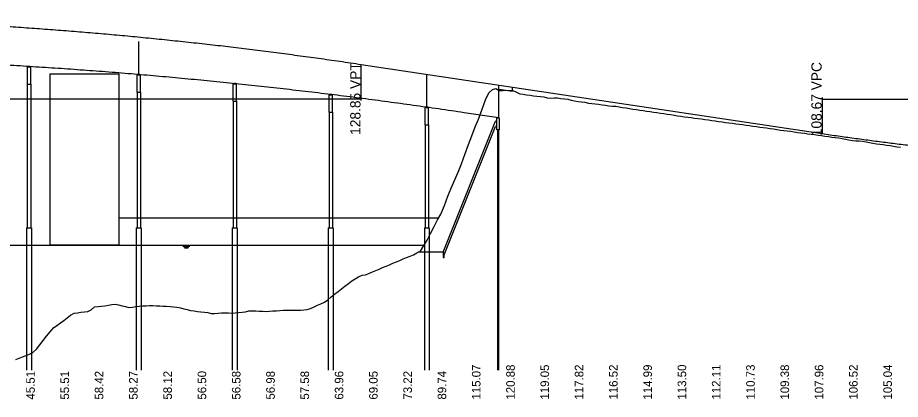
# Model space of a CAD drawing. Extents: x 2121671 to 2169879, y 557274 to 599957.
# Drawn here: x 2155742 to 2157029, y 595763 to 596320 of the extents above; entities that cross this region are included whole.
import ezdxf

# ---------------------------------------------------------------- set-up
doc = ezdxf.new("R2010")
doc.units = 0
for name, color, linetype in [('BR_CONCRETE', 7, 'Continuous'), ('BR_DETAILS', 7, 'Continuous'), ('BR_PRESTRESSED BEAM', 7, 'Continuous'), ('BR_STRUCTURAL STEEL', 7, 'Continuous'), ('RD_DDB_Profile_Elev', 7, 'Continuous'), ('RD_DDB_Profile_EX', 7, 'Continuous'), ('RD_DDB_Profile_PR', 7, 'Continuous'), ('RD_DDB_StripGrade', 7, 'Continuous'), ('RD_DDB_VCLbl', 7, 'Continuous')]:
    doc.layers.add(name, color=color, linetype=linetype)

msp = doc.modelspace()

# ---------------------------------------------------------------- linework, layer by layer
at = {"layer": 'BR_CONCRETE'}
for p, q in [((2155756.3, 596222.8), (2155756.3, 596013.1)), ((2155756.3, 596222.8), (2155756.3, 596013.1)), ((2155761.3, 596222.8), (2155761.3, 596013.1)), ((2155761.3, 596222.8), (2155761.3, 596013.1)), ((2156443.8, 596215.8), (2156463.8, 596212.8)), ((2156443.8, 596215.8), (2156463.8, 596212.8)), ((2156463.8, 596212.8), (2156463.8, 596218.6)), ((2156463.8, 596212.8), (2156463.8, 596218.6)), ((2155916.3, 596211.1), (2155916.3, 596013.1)), ((2155916.3, 596211.1), (2155916.3, 596013.1)), ((2155921.3, 596211.1), (2155921.3, 596013.1)), ((2155921.3, 596211.1), (2155921.3, 596013.1)), ((2156056.3, 596197.9), (2156056.3, 596013.1)), ((2156056.3, 596197.9), (2156056.3, 596013.1)), ((2156061.3, 596197.9), (2156061.3, 596013.1)), ((2156061.3, 596197.9), (2156061.3, 596013.1)), ((2156196.3, 596182), (2156196.3, 596013.1)), ((2156196.3, 596182), (2156196.3, 596013.1)), ((2156201.3, 596182), (2156201.3, 596013.1)), ((2156201.3, 596182), (2156201.3, 596013.1)), ((2156336.3, 596163.4), (2156336.3, 596013.1)), ((2156336.3, 596163.4), (2156336.3, 596013.1)), ((2156341.3, 596163.4), (2156341.3, 596013.1)), ((2156341.3, 596163.4), (2156341.3, 596013.1)), ((2155755.3, 596013.1), (2155755.3, 595805.8)), ((2155755.3, 596013.1), (2155755.3, 595805.8)), ((2155762.3, 596013.1), (2155762.3, 595805.8)), ((2155762.3, 596013.1), (2155762.3, 595805.8)), ((2155915.3, 596013.1), (2155915.3, 595805.8)), ((2155915.3, 596013.1), (2155915.3, 595805.8)), ((2155922.3, 596013.1), (2155922.3, 595805.8)), ((2155922.3, 596013.1), (2155922.3, 595805.8)), ((2156055.3, 596013.1), (2156055.3, 595805.8)), ((2156055.3, 596013.1), (2156055.3, 595805.8)), ((2156062.3, 596013.1), (2156062.3, 595805.8)), ((2156062.3, 596013.1), (2156062.3, 595805.8)), ((2156195.3, 596013.1), (2156195.3, 595805.8)), ((2156195.3, 596013.1), (2156195.3, 595805.8)), ((2156202.3, 596013.1), (2156202.3, 595805.8)), ((2156202.3, 596013.1), (2156202.3, 595805.8)), ((2156335.3, 596013.1), (2156335.3, 595805.8)), ((2156335.3, 596013.1), (2156335.3, 595805.8)), ((2156342.3, 596013.1), (2156342.3, 595805.8)), ((2156342.3, 596013.1), (2156342.3, 595805.8))]:
    msp.add_line(p, q, dxfattribs=at)
for points in [[(2155756.1, 596222.8), (2155761.6, 596222.8), (2155761.6, 596247.8), (2155756.1, 596247.8)], [(2155756.1, 596222.8), (2155761.6, 596222.8), (2155761.6, 596247.8), (2155756.1, 596247.8)], [(2155916.1, 596211.1), (2155921.6, 596211.1), (2155921.6, 596236.1), (2155916.1, 596236.1)], [(2155916.1, 596211.1), (2155921.6, 596211.1), (2155921.6, 596236.1), (2155916.1, 596236.1)], [(2156056.1, 596197.9), (2156061.6, 596197.9), (2156061.6, 596222.9), (2156056.1, 596222.9)], [(2156056.1, 596197.9), (2156061.6, 596197.9), (2156061.6, 596222.9), (2156056.1, 596222.9)], [(2156196.1, 596182), (2156201.6, 596182), (2156201.6, 596207), (2156196.1, 596207)], [(2156196.1, 596182), (2156201.6, 596182), (2156201.6, 596207), (2156196.1, 596207)], [(2156336.1, 596163.4), (2156341.6, 596163.4), (2156341.6, 596188.4), (2156336.1, 596188.4)], [(2156336.1, 596163.4), (2156341.6, 596163.4), (2156341.6, 596188.4), (2156336.1, 596188.4)], [(2156444.5, 596156.3), (2156441, 596156.3), (2156441, 596173.8), (2156444.5, 596173.8)], [(2156444.5, 596156.3), (2156441, 596156.3), (2156441, 596173.8), (2156444.5, 596173.8)]]:
    msp.add_lwpolyline(points, close=True, dxfattribs=at)
at = {"layer": 'BR_DETAILS'}
for p, q in [((2156362.6, 595977.7), (2156439, 596168.8)), ((2156362.6, 595977.7), (2156439, 596168.8)), ((2156441, 596168.8), (2156439, 596168.8)), ((2156441, 596168.8), (2156439, 596168.8)), ((2156364.1, 595974), (2156439, 596161.3)), ((2156364.1, 595974), (2156439, 596161.3)), ((2156441, 596161.3), (2156439, 596161.3)), ((2156441, 596161.3), (2156439, 596161.3)), ((2156362.6, 595977.7), (2156326.5, 595977.7)), ((2156362.6, 595977.7), (2156326.5, 595977.7)), ((2156362.6, 595977.7), (2156362.6, 595970.2)), ((2156362.6, 595977.7), (2156362.6, 595970.2)), ((2156364.1, 595970.2), (2156364.1, 595974)), ((2156364.1, 595970.2), (2156364.1, 595974)), ((2156362.6, 595970.2), (2156364.1, 595970.2)), ((2156362.6, 595970.2), (2156364.1, 595970.2))]:
    msp.add_line(p, q, dxfattribs=at)
for points in [[(2155757.3, 596249.1), (2155758.3, 596249.1), (2155758.3, 596247.8), (2155757.3, 596247.8)], [(2155757.3, 596249.1), (2155758.3, 596249.1), (2155758.3, 596247.8), (2155757.3, 596247.8)], [(2155759.3, 596249.1), (2155760.3, 596249.1), (2155760.3, 596247.8), (2155759.3, 596247.8)], [(2155759.3, 596249.1), (2155760.3, 596249.1), (2155760.3, 596247.8), (2155759.3, 596247.8)], [(2155917.3, 596237.3), (2155918.3, 596237.3), (2155918.3, 596236.1), (2155917.3, 596236.1)], [(2155917.3, 596237.3), (2155918.3, 596237.3), (2155918.3, 596236.1), (2155917.3, 596236.1)], [(2155919.3, 596237.3), (2155920.3, 596237.3), (2155920.3, 596236.1), (2155919.3, 596236.1)], [(2155919.3, 596237.3), (2155920.3, 596237.3), (2155920.3, 596236.1), (2155919.3, 596236.1)], [(2156057.3, 596224.2), (2156058.3, 596224.2), (2156058.3, 596222.9), (2156057.3, 596222.9)], [(2156057.3, 596224.2), (2156058.3, 596224.2), (2156058.3, 596222.9), (2156057.3, 596222.9)], [(2156059.3, 596224.2), (2156060.3, 596224.2), (2156060.3, 596222.9), (2156059.3, 596222.9)], [(2156059.3, 596224.2), (2156060.3, 596224.2), (2156060.3, 596222.9), (2156059.3, 596222.9)], [(2156197.3, 596208.3), (2156198.3, 596208.3), (2156198.3, 596207), (2156197.3, 596207)], [(2156197.3, 596208.3), (2156198.3, 596208.3), (2156198.3, 596207), (2156197.3, 596207)], [(2156199.3, 596208.3), (2156200.3, 596208.3), (2156200.3, 596207), (2156199.3, 596207)], [(2156199.3, 596208.3), (2156200.3, 596208.3), (2156200.3, 596207), (2156199.3, 596207)], [(2156337.3, 596189.7), (2156338.3, 596189.7), (2156338.3, 596188.4), (2156337.3, 596188.4)], [(2156337.3, 596189.7), (2156338.3, 596189.7), (2156338.3, 596188.4), (2156337.3, 596188.4)], [(2156339.3, 596189.7), (2156340.3, 596189.7), (2156340.3, 596188.4), (2156339.3, 596188.4)], [(2156339.3, 596189.7), (2156340.3, 596189.7), (2156340.3, 596188.4), (2156339.3, 596188.4)], [(2156442.2, 596174.2), (2156443.2, 596174.2), (2156443.2, 596173.8), (2156442.2, 596173.8)], [(2156442.2, 596174.2), (2156443.2, 596174.2), (2156443.2, 596173.8), (2156442.2, 596173.8)]]:
    msp.add_lwpolyline(points, close=True, dxfattribs=at)
at = {"layer": 'BR_PRESTRESSED BEAM'}
for p, q in [((2155918.8, 596237.5), (2155918.8, 596285)), ((2155918.8, 596237.5), (2155918.8, 596285)), ((2156338.8, 596189.9), (2156338.8, 596237.4)), ((2156338.8, 596189.9), (2156338.8, 596237.4)), ((2156443.8, 596174.1), (2156443.8, 596221.6)), ((2156443.8, 596174.1), (2156443.8, 596221.6)), ((2156393.2, 596181.7), (2156443.8, 596174.1)), ((2156393.2, 596181.7), (2156443.8, 596174.1)), ((2155755.3, 596013.1), (2155762.3, 596013.1)), ((2155755.3, 596013.1), (2155762.3, 596013.1)), ((2155915.3, 596013.1), (2155922.3, 596013.1)), ((2155915.3, 596013.1), (2155922.3, 596013.1)), ((2156055.3, 596013.1), (2156062.3, 596013.1)), ((2156055.3, 596013.1), (2156062.3, 596013.1)), ((2156195.3, 596013.1), (2156202.3, 596013.1)), ((2156195.3, 596013.1), (2156202.3, 596013.1)), ((2156335.3, 596013.1), (2156342.3, 596013.1)), ((2156335.3, 596013.1), (2156342.3, 596013.1))]:
    msp.add_line(p, q, dxfattribs=at)
msp.add_spline([(2154543.2, 596222.7), (2154580.2, 596226.6), (2154617.2, 596230.2), (2154654.2, 596233.6), (2154691.2, 596236.9), (2154728.2, 596239.9), (2154765.2, 596242.8), (2154802.2, 596245.5), (2154839.2, 596248), (2154876.2, 596250.3), (2154913.2, 596252.4), (2154950.2, 596254.3), (2154987.2, 596256), (2155024.2, 596257.6), (2155061.2, 596258.9), (2155098.2, 596260.1), (2155135.2, 596261.1), (2155172.2, 596261.9), (2155209.2, 596262.5), (2155246.2, 596262.9), (2155283.2, 596263.1), (2155320.2, 596263.1), (2155357.2, 596263), (2155394.2, 596262.6), (2155431.2, 596262.1), (2155468.2, 596261.3), (2155505.2, 596260.4), (2155542.2, 596259.3), (2155579.2, 596258), (2155616.2, 596256.5), (2155653.2, 596254.9), (2155690.2, 596253), (2155727.2, 596251), (2155764.2, 596248.7), (2155801.2, 596246.3), (2155838.2, 596243.7), (2155875.2, 596240.9), (2155912.2, 596237.9), (2155949.2, 596234.7), (2155986.2, 596231.3), (2156023.2, 596227.7), (2156060.2, 596224), (2156097.2, 596220.1), (2156134.2, 596215.9), (2156171.2, 596211.6), (2156208.2, 596207.1), (2156245.2, 596202.4), (2156282.2, 596197.5), (2156319.2, 596192.4), (2156356.2, 596187.2), (2156393.2, 596181.7)], degree=3, dxfattribs=at)
msp.add_spline([(2154543.2, 596222.7), (2154580.2, 596226.6), (2154617.2, 596230.2), (2154654.2, 596233.6), (2154691.2, 596236.9), (2154728.2, 596239.9), (2154765.2, 596242.8), (2154802.2, 596245.5), (2154839.2, 596248), (2154876.2, 596250.3), (2154913.2, 596252.4), (2154950.2, 596254.3), (2154987.2, 596256), (2155024.2, 596257.6), (2155061.2, 596258.9), (2155098.2, 596260.1), (2155135.2, 596261.1), (2155172.2, 596261.9), (2155209.2, 596262.5), (2155246.2, 596262.9), (2155283.2, 596263.1), (2155320.2, 596263.1), (2155357.2, 596263), (2155394.2, 596262.6), (2155431.2, 596262.1), (2155468.2, 596261.3), (2155505.2, 596260.4), (2155542.2, 596259.3), (2155579.2, 596258), (2155616.2, 596256.5), (2155653.2, 596254.9), (2155690.2, 596253), (2155727.2, 596251), (2155764.2, 596248.7), (2155801.2, 596246.3), (2155838.2, 596243.7), (2155875.2, 596240.9), (2155912.2, 596237.9), (2155949.2, 596234.7), (2155986.2, 596231.3), (2156023.2, 596227.7), (2156060.2, 596224), (2156097.2, 596220.1), (2156134.2, 596215.9), (2156171.2, 596211.6), (2156208.2, 596207.1), (2156245.2, 596202.4), (2156282.2, 596197.5), (2156319.2, 596192.4), (2156356.2, 596187.2), (2156393.2, 596181.7)], degree=3, dxfattribs=at)
at = {"layer": 'BR_STRUCTURAL STEEL'}
for p, q in [((2156442.2, 596156.3), (2156442.2, 595805.5)), ((2156442.2, 596156.3), (2156442.2, 595805.5)), ((2156443.3, 596156.3), (2156443.3, 595805.5)), ((2156443.3, 596156.3), (2156443.3, 595805.5))]:
    msp.add_line(p, q, dxfattribs=at)
at = {"layer": 'RD_DDB_Profile_Elev'}
for p, q in [((2155889.7, 596028.1), (2156356.4, 596028.1)), ((2151972, 595988.1), (2156334.9, 595988.1)), ((2155983.2, 595986.8), (2155993.2, 595986.8)), ((2155984.4, 595985.6), (2155991.9, 595985.6)), ((2155985.7, 595984.3), (2155990.7, 595984.3))]:
    msp.add_line(p, q, dxfattribs=at)
msp.add_lwpolyline([(2155789.7, 596238.1), (2155889.7, 596238.1), (2155889.7, 595988.1), (2155789.7, 595988.1)], close=True, dxfattribs=at)
at = {"layer": 'RD_DDB_Profile_EX'}
for points in [[(2156194.5, 595908.4), (2156199.5, 595912.4), (2156204.5, 595916.4), (2156209.5, 595920.4), (2156214.5, 595924.3), (2156219.5, 595928.2), (2156224.5, 595932.1), (2156229.5, 595935.9), (2156234.5, 595939.1), (2156239.5, 595941.9), (2156244.5, 595944.4), (2156249.5, 595944.9), (2156254.5, 595946.9), (2156259.5, 595949), (2156264.5, 595951.1), (2156269.5, 595953.2), (2156274.5, 595955.3), (2156279.5, 595957.4), (2156284.5, 595959.5), (2156289.5, 595961.6), (2156294.5, 595963.7), (2156299.5, 595965.8), (2156304.5, 595967.9), (2156309.5, 595969.9), (2156314.5, 595972), (2156319.5, 595974.1), (2156324.5, 595976.7), (2156329.5, 595979.2), (2156334.5, 595987.3), (2156339.5, 595995.5), (2156344.5, 596005.2), (2156349.5, 596015.4), (2156354.5, 596024.8), (2156359.5, 596033.2), (2156364.5, 596046.1), (2156369.5, 596059.5), (2156374.5, 596071.4), (2156379.5, 596082.4), (2156384.5, 596094.5), (2156389.5, 596106.8), (2156394.5, 596120.1), (2156399.5, 596134.9), (2156404.5, 596147.6), (2156409.5, 596160.6), (2156414.5, 596172), (2156419.5, 596186.4), (2156424.5, 596200.1), (2156429.5, 596210.1), (2156434.5, 596214.9), (2156439.5, 596216.5), (2156444.5, 596213.5), (2156449.5, 596213.7), (2156454.5, 596214.2), (2156459.5, 596213.7), (2156464.5, 596213.7), (2156469.5, 596211.3), (2156474.5, 596209), (2156479.5, 596208.1), (2156484.5, 596207.4), (2156489.5, 596206.6), (2156494.5, 596205.7), (2156499.5, 596205.4), (2156504.5, 596205), (2156509.5, 596204.2), (2156514.5, 596202.8), (2156519.5, 596202.7), (2156524.5, 596202.9), (2156529.5, 596202.8), (2156534.5, 596202.1), (2156539.5, 596201.7), (2156544.5, 596201.2), (2156549.5, 596199.6), (2156554.5, 596198.5), (2156559.5, 596197.8), (2156564.5, 596197.1), (2156569.5, 596196.4), (2156574.5, 596195.4), (2156579.5, 596194.9), (2156584.5, 596194.2), (2156589.5, 596193.5), (2156594.5, 596192.9), (2156599.5, 596192.2), (2156604.5, 596191.3), (2156609.5, 596190.7), (2156614.5, 596190.7), (2156619.5, 596189.9), (2156624.5, 596189), (2156629.5, 596188.2), (2156634.5, 596187.4), (2156639.5, 596186.6), (2156644.5, 596185.8), (2156649.5, 596185.1), (2156654.5, 596184.4), (2156659.5, 596183.7), (2156664.5, 596183), (2156669.5, 596182.2), (2156674.5, 596181.5), (2156679.5, 596180.7), (2156684.5, 596180), (2156689.5, 596179.2), (2156694.5, 596178.5)], [(2156694.5, 596178.5), (2156699.5, 596177.7), (2156704.5, 596176.9), (2156709.5, 596176.2), (2156714.5, 596175.4), (2156719.5, 596174.8), (2156724.5, 596174.1), (2156729.5, 596173.5), (2156734.5, 596172.8), (2156739.5, 596172.1), (2156744.5, 596171.5), (2156749.5, 596170.7), (2156754.5, 596170), (2156759.5, 596169.4), (2156764.5, 596168.6), (2156769.5, 596167.9), (2156774.5, 596167.1), (2156779.5, 596166.4), (2156784.5, 596165.9), (2156789.5, 596165), (2156794.5, 596164.6), (2156799.5, 596163.9), (2156804.5, 596163.2), (2156809.5, 596162.5), (2156814.5, 596161.7), (2156819.5, 596160.9), (2156824.5, 596160.2), (2156829.5, 596159.6), (2156834.5, 596159), (2156839.5, 596158.4), (2156844.5, 596157.6), (2156849.5, 596156.8), (2156854.5, 596155.9), (2156859.5, 596155.3), (2156864.5, 596154.9), (2156869.5, 596154.2), (2156874.5, 596153.4), (2156879.5, 596152.5), (2156884.5, 596151.9), (2156889.5, 596151.2), (2156894.5, 596150.6), (2156899.5, 596150.1), (2156904.5, 596149.4), (2156909.5, 596148.7), (2156914.5, 596147.9), (2156919.5, 596147.1), (2156924.5, 596146.3), (2156929.5, 596145.4), (2156934.5, 596145.3), (2156939.5, 596144.5), (2156944.5, 596143.7), (2156949.5, 596142.7), (2156954.5, 596141.7), (2156959.5, 596140.9), (2156964.5, 596140.4), (2156969.5, 596140), (2156974.5, 596139.5), (2156979.5, 596138.7), (2156984.5, 596137.7), (2156989.5, 596136.6), (2156994.5, 596135.8), (2156999.5, 596135.6), (2157004.5, 596134.8), (2157009.5, 596134.1), (2157014.5, 596133.3), (2157019.5, 596132.4), (2157024.5, 596131.6), (2157029.5, 596131)], [(2155739.5, 595821.3), (2155744.5, 595823.3), (2155749.5, 595825.3), (2155754.5, 595827.2), (2155759.5, 595829.2), (2155764.5, 595831.4), (2155769.5, 595836.2), (2155774.5, 595842.6), (2155779.5, 595849), (2155784.5, 595855.3), (2155789.5, 595861.7), (2155794.5, 595867.2), (2155799.5, 595870.7), (2155804.5, 595874.5), (2155809.5, 595878.3), (2155814.5, 595882.1), (2155819.5, 595886), (2155824.5, 595888.9), (2155829.5, 595889.5), (2155834.5, 595890.1), (2155839.5, 595890.7), (2155844.5, 595891.3), (2155849.5, 595893.7), (2155854.5, 595897.9), (2155859.5, 595898.5), (2155864.5, 595899.1), (2155869.5, 595899.7), (2155874.5, 595900.3), (2155879.5, 595901.4), (2155884.5, 595902), (2155889.5, 595900.8), (2155894.5, 595899.5), (2155899.5, 595898.3), (2155904.5, 595897), (2155909.5, 595897.4), (2155914.5, 595898.5), (2155919.5, 595898.9), (2155924.5, 595899.3), (2155929.5, 595899.7), (2155934.5, 595900.2), (2155939.5, 595899.9), (2155944.5, 595899.7), (2155949.5, 595899.4), (2155954.5, 595899.2), (2155959.5, 595899), (2155964.5, 595898.7), (2155969.5, 595897.9), (2155974.5, 595897.5), (2155979.5, 595896.4), (2155984.5, 595895.2), (2155989.5, 595894.1), (2155994.5, 595892.9), (2155999.5, 595892), (2156004.5, 595891.4), (2156009.5, 595890.9), (2156014.5, 595890.4), (2156019.5, 595889.8), (2156024.5, 595888.5), (2156029.5, 595888.4), (2156034.5, 595888.7), (2156039.5, 595889.1), (2156044.5, 595889.4), (2156049.5, 595889.3), (2156054.5, 595889), (2156059.5, 595889.5), (2156064.5, 595890), (2156069.5, 595890.5), (2156074.5, 595891), (2156079.5, 595892.2), (2156084.5, 595892.3), (2156089.5, 595892.1), (2156094.5, 595891.8), (2156099.5, 595891.6), (2156104.5, 595891.4), (2156109.5, 595891.7), (2156114.5, 595892.1), (2156119.5, 595892.4), (2156124.5, 595892.8), (2156129.5, 595893.2), (2156134.5, 595893.4), (2156139.5, 595893.4), (2156144.5, 595893.4), (2156149.5, 595893.4), (2156154.5, 595893.4), (2156159.5, 595893.5), (2156164.5, 595894.4), (2156169.5, 595895.7), (2156174.5, 595898), (2156179.5, 595900.3), (2156184.5, 595902.5), (2156189.5, 595904.9), (2156194.5, 595908.4)]]:
    msp.add_lwpolyline(points, dxfattribs=at)
at = {"layer": 'RD_DDB_Profile_PR'}
msp.add_line((2156243.2, 596251.7), (2156915.7, 596150.8), dxfattribs=at)
for points in [[(2154693.2, 596286.1), (2154724.2, 596289.3), (2154755.2, 596292.3), (2154786.2, 596295.2), (2154817.2, 596297.9), (2154848.2, 596300.5), (2154879.2, 596302.9), (2154910.2, 596305.1), (2154941.2, 596307.2), (2154972.2, 596309.1), (2155003.2, 596310.9), (2155034.2, 596312.5), (2155065.2, 596314), (2155096.2, 596315.3), (2155127.2, 596316.4), (2155158.2, 596317.4), (2155189.2, 596318.2), (2155220.2, 596318.9), (2155251.2, 596319.4), (2155282.2, 596319.7), (2155313.2, 596319.9), (2155344.2, 596319.9), (2155375.2, 596319.8), (2155406.2, 596319.5), (2155437.2, 596319), (2155468.2, 596318.4), (2155499.2, 596317.7), (2155530.2, 596316.7), (2155561.2, 596315.7), (2155592.2, 596314.4), (2155623.2, 596313), (2155654.2, 596311.4), (2155685.2, 596309.7), (2155716.2, 596307.9), (2155747.2, 596305.8), (2155778.2, 596303.6), (2155809.2, 596301.3), (2155840.2, 596298.8), (2155871.2, 596296.1), (2155902.2, 596293.3), (2155933.2, 596290.3), (2155964.2, 596287.1), (2155995.2, 596283.8), (2156026.2, 596280.4), (2156057.2, 596276.8), (2156088.2, 596273), (2156119.2, 596269), (2156150.2, 596264.9), (2156181.2, 596260.7), (2156212.2, 596256.3), (2156243.2, 596251.7)], [(2156915.7, 596150.8), (2156927.2, 596149.1), (2156938.7, 596147.4), (2156950.2, 596145.8), (2156961.7, 596144.2), (2156973.2, 596142.6), (2156984.7, 596141.1), (2156996.2, 596139.5), (2157007.7, 596138.1), (2157019.2, 596136.6), (2157030.7, 596135.2), (2157042.2, 596133.8), (2157053.7, 596132.4), (2157065.2, 596131.1), (2157076.7, 596129.8), (2157088.2, 596128.5), (2157099.7, 596127.3), (2157111.2, 596126.1), (2157122.7, 596124.9), (2157134.2, 596123.8), (2157145.7, 596122.7), (2157157.2, 596121.6), (2157168.7, 596120.6), (2157180.2, 596119.6), (2157191.7, 596118.6), (2157203.2, 596117.7), (2157214.7, 596116.8), (2157226.2, 596115.9), (2157237.7, 596115), (2157249.2, 596114.2), (2157260.7, 596113.4), (2157272.2, 596112.7), (2157283.7, 596112), (2157295.2, 596111.3), (2157306.7, 596110.6), (2157318.2, 596110), (2157329.7, 596109.4), (2157341.2, 596108.8), (2157352.7, 596108.3), (2157364.2, 596107.8), (2157375.7, 596107.3), (2157387.2, 596106.9), (2157398.7, 596106.5), (2157410.2, 596106.1), (2157421.7, 596105.8), (2157433.2, 596105.5), (2157444.7, 596105.2), (2157456.2, 596105), (2157467.7, 596104.8), (2157479.2, 596104.6), (2157490.7, 596104.4)]]:
    msp.add_spline(points, degree=3, dxfattribs=at)
at = {"layer": 'RD_DDB_VCLbl'}
for p, q in [((2156243.2, 596199.2), (2156243.2, 596251.7)), ((2156915.7, 596203.3), (2156915.7, 596150.8)), ((2154693.2, 596201.7), (2156243.2, 596201.7)), ((2156915.7, 596200.8), (2157490.7, 596200.8))]:
    msp.add_line(p, q, dxfattribs=at)

# ---------------------------------------------------------------- texts
at = {"layer": 'RD_DDB_StripGrade'}
for s, height, p in [('108.67 VPC', 15, (2156914.7, 596147)), ('128.85 VPT', 15, (2156242.2, 596148.9)), ('56.50', 12.5, (2156017.2, 595762.7)), ('69.05', 12.5, (2156267.2, 595762.7)), ('89.74', 12.5, (2156367.2, 595762.7)), ('115.07', 12.5, (2156417.2, 595762.7)), ('120.88', 12.5, (2156467.2, 595762.7)), ('119.05', 12.5, (2156517.2, 595762.7)), ('117.82', 12.5, (2156567.2, 595762.7)), ('116.52', 12.5, (2156617.2, 595762.7)), ('114.99', 12.5, (2156667.2, 595762.7)), ('113.50', 12.5, (2156717.2, 595762.7)), ('112.11', 12.5, (2156767.2, 595762.7)), ('110.73', 12.5, (2156817.2, 595762.7)), ('109.38', 12.5, (2156867.2, 595762.7)), ('107.96', 12.5, (2156917.2, 595762.7)), ('106.52', 12.5, (2156967.2, 595762.7)), ('105.04', 12.5, (2157017.2, 595762.7)), ('45.51', 12.5, (2155767.2, 595762.7)), ('55.51', 12.5, (2155817.2, 595762.7)), ('58.42', 12.5, (2155867.2, 595762.7)), ('58.27', 12.5, (2155917.2, 595762.7)), ('58.12', 12.5, (2155967.2, 595762.7)), ('56.58', 12.5, (2156067.2, 595762.7)), ('56.98', 12.5, (2156117.2, 595762.7)), ('57.58', 12.5, (2156167.2, 595762.7)), ('63.96', 12.5, (2156217.2, 595762.7)), ('73.22', 12.5, (2156317.2, 595762.7))]:
    msp.add_text(s, height=height, rotation=90, dxfattribs=at).set_placement(p)

doc.saveas('drawing.dxf')
